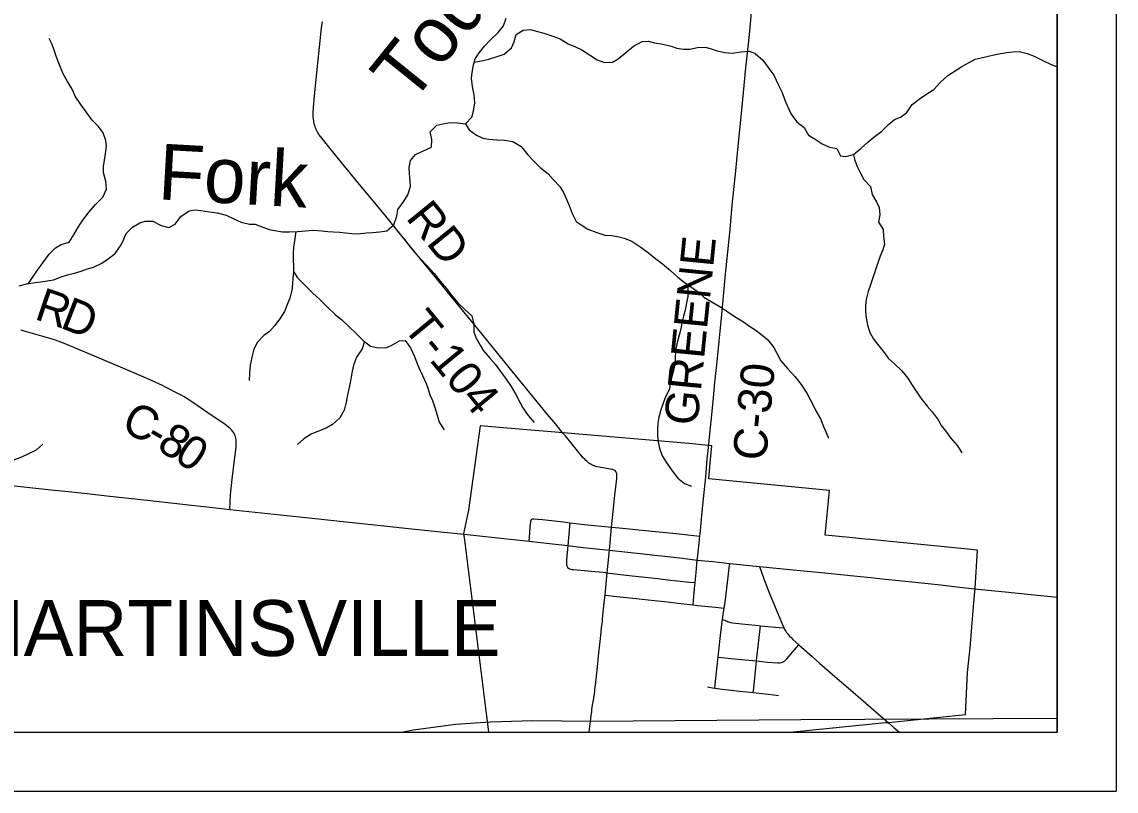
# Model space of a CAD drawing. Extents: x 0 to 34, y 0 to 22.
# Drawn here: x 7.143 to 9, y 14 to 15.305 of the extents above; entities that cross this region are included whole.
import ezdxf

# ---------------------------------------------------------------- set-up
doc = ezdxf.new("R2010")
doc.units = 0
for name, color, linetype in [('Default', 7, 'Continuous'), ('GM_X_City_Street', 7, 'Continuous'), ('GM_X_Corporation_Text', 7, 'Continuous'), ('GM_X_County_Road', 7, 'Continuous'), ('GM_X_County_Road_Text', 7, 'Continuous'), ('GM_X_Minor_River', 7, 'Continuous'), ('GM_X_Minor_River_Text', 7, 'Continuous'), ('GM_X_Rail_Line', 7, 'Continuous'), ('GM_X_State_Route', 7, 'Continuous'), ('GM_X_Township_Road', 7, 'Continuous'), ('GM_X_Township_Road_Text', 7, 'Continuous'), ('SH_Data', 7, 'Continuous')]:
    doc.layers.add(name, color=color, linetype=linetype)

msp = doc.modelspace()

# ---------------------------------------------------------------- linework, layer by layer
at = {"layer": 'Default'}
msp.add_lwpolyline([(7.935, 14.1), (8.4464, 14.1), (8.6087, 14.1161), (8.614, 14.1165), (8.7447, 14.1301), (8.7479, 14.2014), (8.7526, 14.2431), (8.758, 14.3129), (8.7606, 14.3441), (8.7648, 14.4085), (8.6743, 14.4175), (8.6338, 14.4216), (8.5887, 14.4261), (8.568, 14.4281), (8.5533, 14.4296), (8.5303, 14.4319), (8.5065, 14.4343), (8.5138, 14.51), (8.3087, 14.5298), (8.3107, 14.5504), (8.3142, 14.5857), (8.2753, 14.5895), (8.0619, 14.6076), (8.0551, 14.6081), (8.0004, 14.6128), (7.9212, 14.6195), (7.9013, 14.4763), (7.894, 14.4419), (7.8928, 14.4362), (7.8938, 14.4299), (7.9316, 14.1272), (7.9333, 14.114)], close=True, dxfattribs=at)
at = {"layer": 'GM_X_City_Street'}
for points in [[(8.0041, 14.424), (8.0046, 14.43), (8.006, 14.4479), (8.007, 14.4572), (8.0072, 14.4582), (8.0074, 14.459), (8.0078, 14.46), (8.0082, 14.4607), (8.0088, 14.4613), (8.0096, 14.4618), (8.0105, 14.462), (8.0113, 14.4621), (8.0121, 14.4621), (8.0269, 14.4605), (8.0625, 14.4565), (8.0731, 14.4553), (8.0981, 14.4524), (8.1441, 14.4475), (8.1567, 14.4463), (8.2074, 14.4416), (8.2185, 14.4405), (8.2536, 14.4368), (8.2887, 14.4331), (8.2938, 14.4326)], [(8.0731, 14.4553), (8.0725, 14.4487), (8.0697, 14.4165), (8.0675, 14.3919), (8.0673, 14.3894), (8.0672, 14.3871), (8.0673, 14.3851), (8.0676, 14.3832), (8.0684, 14.3809), (8.0694, 14.3794), (8.0708, 14.3782), (8.0724, 14.3773), (8.0748, 14.3765), (8.0767, 14.3761), (8.0791, 14.3758), (8.0853, 14.3753), (8.1045, 14.3738), (8.1094, 14.3733), (8.1298, 14.3712), (8.1364, 14.3703), (8.1396, 14.3699), (8.1642, 14.3668), (8.179, 14.3651), (8.2222, 14.3604), (8.2346, 14.3588), (8.2438, 14.3578), (8.2549, 14.3566), (8.2769, 14.3545), (8.2857, 14.3536)], [(8.2821, 14.316), (8.2828, 14.3241), (8.2853, 14.3491), (8.2857, 14.3536), (8.2872, 14.3707), (8.2894, 14.392)], [(8.3189, 14.1748), (8.3195, 14.1804), (8.3237, 14.2174), (8.3246, 14.2272), (8.3251, 14.2328), (8.3295, 14.2692), (8.3324, 14.2911), (8.3335, 14.2993), (8.3352, 14.3105), (8.3367, 14.3202), (8.3437, 14.3782), (8.3446, 14.3862)], [(8.1328, 14.3325), (8.153, 14.3303), (8.1855, 14.3267), (8.2114, 14.3238), (8.2336, 14.3214), (8.2614, 14.3184), (8.2821, 14.316), (8.2898, 14.3151), (8.32, 14.312), (8.3352, 14.3105)], [(8.3324, 14.2911), (8.3398, 14.288), (8.3415, 14.2873), (8.3438, 14.2866), (8.346, 14.2859), (8.3493, 14.2853), (8.3543, 14.2847), (8.3704, 14.2832), (8.3939, 14.2807), (8.3968, 14.2804), (8.4026, 14.28), (8.4281, 14.2778), (8.4361, 14.2771)], [(8.3843, 14.167), (8.3852, 14.1747), (8.39, 14.2208), (8.3906, 14.226), (8.3962, 14.2754), (8.3968, 14.2804)], [(8.3246, 14.2272), (8.3584, 14.2238), (8.39, 14.2208), (8.3987, 14.2199), (8.4086, 14.2188), (8.426, 14.2176), (8.4277, 14.2176), (8.4297, 14.2177), (8.4322, 14.2181), (8.4339, 14.2186), (8.4351, 14.2191), (8.4361, 14.2197), (8.4373, 14.2204), (8.4386, 14.2215), (8.4413, 14.2241), (8.4577, 14.2437), (8.4614, 14.2482)], [(8.3066, 14.1766), (8.3152, 14.1754), (8.3189, 14.1748), (8.3317, 14.173), (8.3421, 14.1717), (8.3558, 14.17), (8.3792, 14.1676), (8.3843, 14.167), (8.4094, 14.1644), (8.4193, 14.1633), (8.4233, 14.1629), (8.4273, 14.162)]]:
    msp.add_lwpolyline(points, dxfattribs=at)
at = {"layer": 'GM_X_County_Road'}
for p, q in [((8.1364, 14.3703), (8.1403, 14.4087)), ((8.6137, 14.1159), (8.6237, 14.1074)), ((8.6237, 14.1074), (8.6324, 14.1))]:
    msp.add_line(p, q, dxfattribs=at)
for points in [[(8.3085, 14.583), (8.3113, 14.6114), (8.3134, 14.6324), (8.3169, 14.667), (8.3194, 14.693), (8.3214, 14.7134), (8.3224, 14.7223), (8.3263, 14.7633), (8.3287, 14.7861), (8.3302, 14.8022), (8.3331, 14.8332), (8.3373, 14.877), (8.3449, 14.9524), (8.3488, 14.9939), (8.3545, 15.052), (8.3583, 15.0884), (8.3649, 15.1552), (8.3719, 15.2268), (8.3762, 15.2676), (8.3784, 15.2892), (8.383, 15.3405)], [(7.4964, 14.4779), (7.4975, 14.5027), (7.5004, 14.5293), (7.5043, 14.562), (7.5068, 14.5835), (7.507, 14.5871), (7.5072, 14.5909), (7.507, 14.5952), (7.5065, 14.5988), (7.5058, 14.6017), (7.5049, 14.604), (7.5042, 14.6056), (7.503, 14.6078), (7.5014, 14.6102), (7.4991, 14.6129), (7.4973, 14.6146), (7.4946, 14.617), (7.4877, 14.6222), (7.4682, 14.6356), (7.4316, 14.6602), (7.4247, 14.6646), (7.4185, 14.6685), (7.4134, 14.6714), (7.4078, 14.6746), (7.4015, 14.6779), (7.3962, 14.6807), (7.3885, 14.6845), (7.3818, 14.6878), (7.3569, 14.6992), (7.3256, 14.7127), (7.2307, 14.7531), (7.221, 14.757), (7.214, 14.7598), (7.2061, 14.7627), (7.2006, 14.7648), (7.193, 14.7671), (7.1852, 14.7695), (7.1416, 14.7821)], [(8.3036, 14.533), (8.3049, 14.5483), (8.3064, 14.5631), (8.3085, 14.583)], [(8.2938, 14.4326), (8.2947, 14.442), (8.2978, 14.4736), (8.3, 14.4958), (8.3036, 14.533)], [(8.2894, 14.392), (8.2903, 14.3999), (8.2927, 14.4209), (8.2938, 14.4326)], [(8.1328, 14.3325), (8.1351, 14.3577), (8.1364, 14.3703)], [(8.3948, 14.3809), (8.4024, 14.3603), (8.411, 14.3383), (8.4133, 14.3325), (8.4258, 14.3014), (8.4344, 14.2807), (8.4361, 14.2771)], [(8.1061, 14.1), (8.1066, 14.1048), (8.1072, 14.1099), (8.1082, 14.1183), (8.1087, 14.1227), (8.1095, 14.1286), (8.1102, 14.1343), (8.1107, 14.1387), (8.1118, 14.1457), (8.1131, 14.1541), (8.1148, 14.1649), (8.1154, 14.1682), (8.1158, 14.1722), (8.1173, 14.1842), (8.1195, 14.2051), (8.1226, 14.2346), (8.1248, 14.254), (8.1262, 14.2693), (8.1271, 14.2774), (8.1278, 14.2835), (8.1283, 14.2884), (8.1287, 14.2925), (8.1305, 14.3089), (8.132, 14.3243), (8.1328, 14.3325)], [(8.4361, 14.2771), (8.4374, 14.2744), (8.4395, 14.2712), (8.4407, 14.2693), (8.4421, 14.2677), (8.4438, 14.2655), (8.4461, 14.2628), (8.4484, 14.2603), (8.4517, 14.257), (8.4563, 14.2528), (8.4614, 14.2482)], [(8.4614, 14.2482), (8.4843, 14.2281), (8.4974, 14.2166), (8.5053, 14.2096), (8.5269, 14.191), (8.5452, 14.175), (8.6054, 14.123), (8.6137, 14.1159)]]:
    msp.add_lwpolyline(points, dxfattribs=at)
at = {"layer": 'GM_X_Minor_River'}
for points in [[(7.7982, 15.0115), (7.8029, 15.0255), (7.8023, 15.0358), (7.801, 15.0472), (7.8003, 15.0578), (7.8028, 15.0696), (7.8113, 15.0797), (7.825, 15.086), (7.8384, 15.0923), (7.839, 15.1052), (7.8361, 15.1181), (7.8476, 15.1297), (7.8575, 15.1319), (7.8701, 15.134), (7.8826, 15.1334), (7.8963, 15.1317), (7.9067, 15.1434), (7.9095, 15.1536), (7.912, 15.1676), (7.9106, 15.1813), (7.9078, 15.1954), (7.9061, 15.2094), (7.9073, 15.2189), (7.9094, 15.2322), (7.9126, 15.242), (7.9195, 15.2522), (7.9284, 15.2638), (7.9377, 15.2739), (7.9515, 15.2867), (7.9608, 15.2983), (7.9652, 15.3112)], [(7.9108, 15.2365), (7.9258, 15.2392), (7.9357, 15.2417), (7.9479, 15.2453), (7.9617, 15.2501), (7.9744, 15.2609), (7.9787, 15.2711), (7.9823, 15.2832), (7.9941, 15.291), (8.0063, 15.2917), (8.0161, 15.2889), (8.029, 15.2857), (8.0441, 15.2805), (8.057, 15.2758), (8.0702, 15.2677), (8.0826, 15.2626), (8.0932, 15.2571), (8.1064, 15.249), (8.1196, 15.2405), (8.132, 15.2361), (8.1453, 15.2363), (8.1549, 15.2419), (8.1683, 15.2527), (8.1814, 15.2636), (8.1959, 15.2717), (8.2058, 15.272), (8.2168, 15.2692), (8.2308, 15.2671), (8.2448, 15.2635), (8.2547, 15.26), (8.2657, 15.2587), (8.2767, 15.2585), (8.2896, 15.2614), (8.3033, 15.262), (8.3131, 15.2592), (8.323, 15.2557), (8.3362, 15.2528), (8.3487, 15.2519), (8.364, 15.254), (8.3777, 15.2553), (8.3875, 15.2514), (8.4006, 15.2399), (8.4096, 15.2276), (8.4193, 15.2142), (8.4274, 15.1974), (8.4333, 15.1851), (8.4377, 15.1718), (8.4443, 15.1577), (8.4488, 15.1481), (8.4581, 15.1355), (8.4709, 15.1258), (8.4779, 15.1128), (8.4896, 15.1058), (8.5013, 15.0977), (8.5137, 15.0922), (8.5262, 15.0902), (8.5321, 15.0776), (8.5416, 15.0767), (8.5546, 15.0796), (8.5673, 15.0904), (8.5792, 15.1016), (8.5892, 15.1091), (8.6026, 15.1196), (8.6145, 15.1315), (8.6241, 15.139), (8.6341, 15.1434), (8.6448, 15.1513), (8.6541, 15.1648), (8.6679, 15.1753), (8.6806, 15.1838), (8.6905, 15.1902), (8.7013, 15.2022), (8.7144, 15.2141), (8.727, 15.2216), (8.7385, 15.229), (8.7508, 15.2361), (8.7611, 15.2413), (8.771, 15.2438), (8.7904, 15.2485), (8.8041, 15.2509), (8.8148, 15.2527), (8.8247, 15.2541), (8.8353, 15.2543), (8.849, 15.2511), (8.8607, 15.2464), (8.8754, 15.2394), (8.8878, 15.2339), (8.9, 15.2284)], [(7.1546, 14.861), (7.1612, 14.871), (7.1698, 14.8834), (7.1806, 14.8981), (7.1899, 14.9105), (7.2007, 14.9217), (7.2102, 14.9273), (7.2236, 14.9313), (7.2321, 14.9448), (7.2403, 14.958), (7.2469, 14.9682), (7.2577, 14.9825), (7.2685, 14.9949), (7.2808, 15.0076), (7.2867, 15.0208), (7.2861, 15.0345), (7.2821, 15.049), (7.2819, 15.0592), (7.2835, 15.0702), (7.2852, 15.0808), (7.2869, 15.0937), (7.2859, 15.1036), (7.2815, 15.1165), (7.2726, 15.128), (7.2628, 15.138), (7.2535, 15.1503), (7.2434, 15.1649), (7.2341, 15.179), (7.2286, 15.1909), (7.2208, 15.2035), (7.2137, 15.2169), (7.2075, 15.2318), (7.202, 15.2451), (7.1983, 15.2566), (7.1946, 15.2665), (7.1895, 15.2768)], [(7.8963, 15.1317), (7.9026, 15.1218), (7.915, 15.1129), (7.9256, 15.1078), (7.9358, 15.1058), (7.9491, 15.1045), (7.9624, 15.1039), (7.9764, 15.1019), (7.9907, 15.0933), (8.0016, 15.0795), (8.012, 15.0684), (8.0229, 15.058), (8.0361, 15.0472), (8.0451, 15.0376), (8.0563, 15.0253), (8.0622, 15.0153), (8.067, 15.0054), (8.0718, 14.9936), (8.0769, 14.9798), (8.0836, 14.9661), (8.0938, 14.9595), (8.1039, 14.9533), (8.1191, 14.9474), (8.1323, 14.9431), (8.1437, 14.9422), (8.1539, 14.9409), (8.1653, 14.9381), (8.1781, 14.933), (8.1935, 14.9225), (8.2067, 14.9129), (8.2191, 14.9028), (8.2296, 14.8947), (8.2443, 14.8824), (8.2563, 14.872), (8.2672, 14.8631), (8.2792, 14.855), (8.2901, 14.8473), (8.3007, 14.8376), (8.3157, 14.8287), (8.3293, 14.8209), (8.341, 14.8128), (8.3538, 14.8047), (8.3677, 14.7958), (8.3779, 14.7888), (8.3895, 14.7811), (8.3993, 14.7733), (8.4091, 14.7652), (8.4195, 14.7522), (8.4243, 14.7426), (8.4314, 14.7296), (8.4422, 14.717), (8.455, 14.7035), (8.4658, 14.6897), (8.4755, 14.6748), (8.481, 14.6645), (8.4862, 14.6545), (8.4906, 14.645), (8.4984, 14.6316), (8.5036, 14.6182), (8.508, 14.6083), (8.5121, 14.5988)], [(8.5542, 15.0795), (8.5567, 15.07), (8.5608, 15.0594), (8.5667, 15.0468), (8.5719, 15.0372), (8.5835, 15.0253), (8.5863, 15.012), (8.5934, 14.9997), (8.5982, 14.9898), (8.5992, 14.9776), (8.5971, 14.9651), (8.6045, 14.9525), (8.6051, 14.9407), (8.6072, 14.9278), (8.6041, 14.918), (8.5997, 14.9074), (8.5962, 14.8976), (8.5914, 14.8824), (8.5831, 14.8586), (8.5792, 14.8477), (8.576, 14.8341), (8.5747, 14.8238), (8.5749, 14.8136), (8.5759, 14.8029), (8.5784, 14.7904), (8.5824, 14.7778), (8.5876, 14.7679), (8.5951, 14.7579), (8.6067, 14.7441), (8.6134, 14.7345), (8.6239, 14.7249), (8.6363, 14.7129), (8.6467, 14.7003), (8.6527, 14.6903), (8.6616, 14.6765), (8.6687, 14.6666), (8.6795, 14.6528), (8.6881, 14.6432), (8.6978, 14.6298), (8.7034, 14.6202), (8.712, 14.6091), (8.7191, 14.5991), (8.7307, 14.5857), (8.7385, 14.5738)], [(7.1386, 14.8568), (7.1516, 14.8605), (7.1657, 14.8629), (7.1756, 14.864), (7.1862, 14.8653), (7.1969, 14.8675), (7.2099, 14.8722), (7.2209, 14.8759), (7.2327, 14.8788), (7.2442, 14.882), (7.2549, 14.8857), (7.2652, 14.889), (7.2789, 14.8956), (7.29, 14.9027), (7.3019, 14.9117), (7.3116, 14.9264), (7.3163, 14.9362), (7.3206, 14.946), (7.331, 14.9568), (7.3433, 14.9639), (7.3528, 14.9668), (7.3657, 14.9666), (7.3797, 14.9593), (7.3929, 14.956), (7.4033, 14.9616), (7.4133, 14.9744), (7.4275, 14.9844), (7.4374, 14.9858), (7.4469, 14.9846), (7.462, 14.9825), (7.4749, 14.9808), (7.4901, 14.9768), (7.5018, 14.9713), (7.5157, 14.9651), (7.5298, 14.9619), (7.5392, 14.9617), (7.5494, 14.9578), (7.5627, 14.9527), (7.5725, 14.9511), (7.5854, 14.9486), (7.5968, 14.9485), (7.6109, 14.9494), (7.6246, 14.9504), (7.6371, 14.9514), (7.6523, 14.9504), (7.6625, 14.9495), (7.6724, 14.9486), (7.6826, 14.9481), (7.6925, 14.9469), (7.7031, 14.946), (7.7141, 14.9454), (7.7282, 14.9472), (7.7381, 14.9478), (7.751, 14.9488), (7.7628, 14.9501), (7.7747, 14.9606), (7.7795, 14.9753), (7.7812, 14.9867), (7.7908, 14.9995), (7.7982, 15.0115)], [(7.6084, 14.9493), (7.6057, 14.9336), (7.6044, 14.9226), (7.6035, 14.9123), (7.6038, 14.9013), (7.6044, 14.8907), (7.6042, 14.88), (7.6034, 14.8706), (7.6028, 14.8607), (7.6016, 14.8497), (7.598, 14.8361), (7.594, 14.8263), (7.5889, 14.8138), (7.5812, 14.801), (7.5723, 14.7894), (7.5634, 14.7796), (7.5538, 14.7729), (7.5434, 14.7613), (7.5372, 14.7496), (7.5336, 14.7363), (7.5307, 14.7227), (7.5294, 14.7091), (7.5292, 14.6965)], [(7.7736, 14.9596), (7.7829, 14.9468), (7.7915, 14.9372), (7.8012, 14.9246), (7.8091, 14.915), (7.8199, 14.9031), (7.8308, 14.8908), (7.8427, 14.8781), (7.8532, 14.8647), (7.8637, 14.8524), (7.8741, 14.839), (7.8839, 14.8275), (7.8951, 14.8167), (7.9067, 14.8063), (7.91, 14.7926), (7.9102, 14.7789), (7.9135, 14.7694), (7.9209, 14.7564), (7.9268, 14.7468), (7.9381, 14.7338), (7.9463, 14.7242), (7.9556, 14.7119), (7.9649, 14.6989), (7.9735, 14.6862), (7.9813, 14.6725), (7.9883, 14.6598), (7.9935, 14.6499), (8.0025, 14.6373), (8.0126, 14.6254)], [(7.6043, 14.8816), (7.6113, 14.8705), (7.6241, 14.8574), (7.6372, 14.8447), (7.6485, 14.8347), (7.6616, 14.8212), (7.6754, 14.8081), (7.6856, 14.8), (7.6976, 14.7885), (7.7107, 14.7762), (7.7223, 14.7646), (7.7347, 14.7546), (7.748, 14.7518), (7.7628, 14.7527), (7.7724, 14.7568), (7.7842, 14.7638), (7.7937, 14.7641), (7.8027, 14.7518), (7.8093, 14.7373), (7.8138, 14.7266), (7.8174, 14.7167), (7.8233, 14.7049), (7.8292, 14.6915), (7.8325, 14.682), (7.8358, 14.6721), (7.8399, 14.6625), (7.8443, 14.6507), (7.8483, 14.6377), (7.8515, 14.6259), (7.8597, 14.6129)], [(8.2732, 14.8591), (8.2733, 14.8391), (8.2709, 14.8285), (8.2688, 14.8156), (8.266, 14.8058), (8.2629, 14.7941), (8.2612, 14.7835), (8.2584, 14.7733), (8.2552, 14.7608), (8.2528, 14.7494), (8.2518, 14.7373), (8.2521, 14.7274), (8.2489, 14.7134), (8.2461, 14.7032), (8.2432, 14.6915), (8.242, 14.6816), (8.2357, 14.6688), (8.2314, 14.6582), (8.2279, 14.6484), (8.2243, 14.6344), (8.2226, 14.6242), (8.2217, 14.6132), (8.2219, 14.6033), (8.2229, 14.5923), (8.2254, 14.5816), (8.2298, 14.5686), (8.2376, 14.556), (8.247, 14.543), (8.2563, 14.5307), (8.2676, 14.5215), (8.2797, 14.5175)], [(7.7249, 14.7626), (7.721, 14.7502), (7.7109, 14.7359), (7.7058, 14.7223), (7.7038, 14.7125), (7.7013, 14.6985), (7.6985, 14.6848), (7.6957, 14.6724), (7.6936, 14.6599), (7.6904, 14.6462), (7.6826, 14.6334), (7.6707, 14.6218), (7.6596, 14.6159), (7.6466, 14.6107), (7.6344, 14.6052), (7.6217, 14.5974), (7.6113, 14.5877)], [(7.1286, 14.5613), (7.1435, 14.5668), (7.1538, 14.5723), (7.168, 14.5786), (7.1791, 14.5883)]]:
    msp.add_lwpolyline(points, dxfattribs=at)
at = {"layer": 'GM_X_Rail_Line'}
msp.add_lwpolyline([(7.7874, 14.1), (7.808, 14.1042), (7.8789, 14.1135), (7.9379, 14.1176), (8.0106, 14.1199), (8.1095, 14.1188), (8.4651, 14.1216), (8.9, 14.1235)], dxfattribs=at)
at = {"layer": 'GM_X_State_Route'}
for points in [[(7.0944, 14.5218), (7.1933, 14.5113), (7.2279, 14.5076), (7.2544, 14.5046), (7.2878, 14.5009), (7.3612, 14.4927), (7.4013, 14.4883), (7.431, 14.485), (7.4724, 14.4806), (7.4964, 14.4779), (7.6361, 14.4631), (7.6935, 14.4567), (7.7417, 14.4517), (7.8103, 14.4443), (7.8932, 14.4357)], [(7.8932, 14.4357), (7.9095, 14.4343), (7.9614, 14.4287), (8.0041, 14.424), (8.0435, 14.4195), (8.0697, 14.4165), (8.0866, 14.4146)], [(8.0866, 14.4146), (8.1015, 14.4129), (8.1403, 14.4087)], [(8.1403, 14.4087), (8.1978, 14.4022), (8.2225, 14.3996)], [(8.2225, 14.3996), (8.2284, 14.3989), (8.2642, 14.3949), (8.2894, 14.392), (8.316, 14.3893), (8.3446, 14.3862), (8.3948, 14.3809), (8.4522, 14.3751), (8.5056, 14.3701), (8.5549, 14.3651)], [(8.5549, 14.3651), (8.5836, 14.3622), (8.6089, 14.3595), (8.6812, 14.3521), (8.7022, 14.3497), (8.7251, 14.3471), (8.7597, 14.3432)], [(8.7597, 14.3432), (8.812, 14.3379), (8.8503, 14.3338), (8.9, 14.3287)]]:
    msp.add_lwpolyline(points, dxfattribs=at)
at = {"layer": 'GM_X_Township_Road'}
msp.add_line((8.1403, 14.4087), (8.1441, 14.4475), dxfattribs=at)
msp.add_lwpolyline([(5.5061, 14.1), (8.9, 14.1), (8.9, 16.5763), (8.8995, 16.5764), (8.8816, 16.5789), (8.8447, 16.5834), (8.8399, 16.5839), (7.6646, 16.0363), (6.8121, 15.6375), (6.7874, 15.6255), (6.2381, 14.9624), (5.7089, 14.3412), (5.6307, 14.246)], close=True, dxfattribs=at)
for points in [[(8.0613, 14.6074), (8.0492, 14.6223), (8.0353, 14.639), (7.963, 14.7276), (7.9414, 14.754), (7.9171, 14.7839), (7.8722, 14.8386), (7.8575, 14.8564), (7.8421, 14.8751), (7.8034, 14.9229), (7.7842, 14.9465), (7.7608, 14.9755), (7.7424, 14.9981), (7.7137, 15.0324), (7.6734, 15.0813), (7.6504, 15.1099), (7.6474, 15.1139), (7.6452, 15.1177), (7.6439, 15.1202), (7.643, 15.1223), (7.6418, 15.1248), (7.6409, 15.1275), (7.6401, 15.1303), (7.6394, 15.1324), (7.6389, 15.1347), (7.6385, 15.1367), (7.6381, 15.1397), (7.6377, 15.1429), (7.6376, 15.1466), (7.6376, 15.1498), (7.6378, 15.1537), (7.638, 15.1572), (7.6382, 15.1604), (7.6399, 15.1796), (7.6457, 15.2346), (7.6514, 15.289), (7.6526, 15.2989), (7.6534, 15.305)], [(8.1441, 14.4475), (8.1479, 14.4849), (8.1497, 14.5021), (8.1527, 14.5299), (8.153, 14.5342), (8.1529, 14.5359), (8.1529, 14.5372), (8.1527, 14.5385), (8.1525, 14.5395), (8.1519, 14.541), (8.151, 14.5424), (8.1499, 14.5436), (8.1485, 14.5445), (8.1474, 14.545), (8.1463, 14.5453), (8.1444, 14.5458), (8.1422, 14.5462), (8.1256, 14.5488), (8.1195, 14.5502), (8.1169, 14.5508), (8.1146, 14.5517), (8.1126, 14.5525), (8.1105, 14.5534), (8.1088, 14.5543), (8.1072, 14.5553), (8.1055, 14.5564), (8.1036, 14.5578), (8.1018, 14.5594), (8.1003, 14.5608), (8.0984, 14.5628), (8.096, 14.5654), (8.0861, 14.5774), (8.0656, 14.6024), (8.0613, 14.6074)]]:
    msp.add_lwpolyline(points, dxfattribs=at)
at = {"layer": 'SH_Data'}
for p, q in [((9, 21), (9, 14)), ((8.9, 20.9), (8.9, 14.1)), ((2.1, 14.1), (8.9, 14.1)), ((2, 14), (9, 14))]:
    msp.add_line(p, q, dxfattribs=at)

# ---------------------------------------------------------------- texts
at = {"layer": 'GM_X_Corporation_Text'}
msp.add_text('MARTINSVILLE', height=0.094697, rotation=0, dxfattribs=at).set_placement((7.0409, 14.2292))
at = {"layer": 'GM_X_County_Road_Text'}
for s, height, rotation, p in [('GREENE', 0.05682, 84.324, (8.2895, 14.6187)), ('R', 0.0568, 341.4342, (7.1629, 14.8012)), ('D', 0.0568, 338.827, (7.2065, 14.7865)), ('C-30', 0.05682, 84.5353, (8.4058, 14.5591)), ('C', 0.0568, 333.8539, (7.3094, 14.6125)), ('-', 0.0568, 330.4943, (7.3505, 14.5923)), ('8', 0.0568, 327.1716, (7.37, 14.5813)), ('0', 0.0568, 326.5856, (7.3993, 14.5624))]:
    msp.add_text(s, height=height, rotation=rotation, dxfattribs=at).set_placement(p)
at = {"layer": 'GM_X_Minor_River_Text'}
for s, height, rotation, p in [('Todds', 0.09469, 51.0511, (7.8034, 15.1628)), ('Fork', 0.0947, 356.769, (7.3732, 15.0039))]:
    msp.add_text(s, height=height, rotation=rotation, dxfattribs=at).set_placement(p)
at = {"layer": 'GM_X_Township_Road_Text'}
for s, rotation, p in [('RD', 309.1177, (7.7936, 14.9719)), ('T-104', 309.4482, (7.7878, 14.7867))]:
    msp.add_text(s, height=0.05682, rotation=rotation, dxfattribs=at).set_placement(p)

doc.saveas('drawing.dxf')
